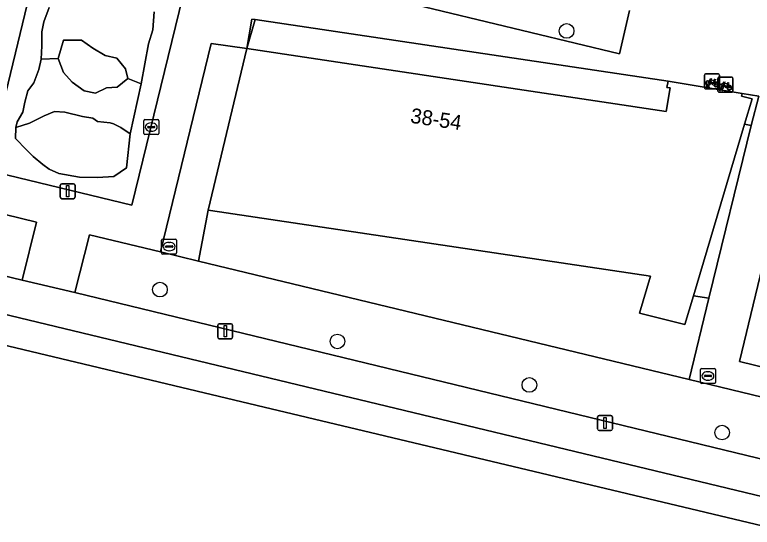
# Model space of a CAD drawing. Extents: x 162803 to 163818, y 381639 to 382475.
# Drawn here: x 163361.88 to 163411.14, y 382135.2 to 382169.41 of the extents above; entities that cross this region are included whole.
import ezdxf

# ---------------------------------------------------------------- set-up
doc = ezdxf.new("R2010")
doc.units = 0
for name, color, linetype in [('IMGEO_Boom', 7, 'Continuous'), ('IMGEO_Erf', 7, 'Continuous'), ('IMGEO_Fietsenrek', 7, 'Continuous'), ('IMGEO_Groenvoorziening', 7, 'Continuous'), ('IMGEO_Kolk', 7, 'Continuous'), ('IMGEO_Lichtmast', 7, 'Continuous'), ('IMGEO_Pand', 7, 'Continuous'), ('IMGEO_Pand_nummerreeks', 7, 'Continuous'), ('IMGEO_Pand_overbouw', 7, 'Continuous'), ('IMGEO_Parkeervlak_open', 7, 'Continuous'), ('IMGEO_Rioolput', 7, 'Continuous'), ('IMGEO_Voetpad_open', 7, 'Continuous')]:
    doc.layers.add(name, color=color, linetype=linetype)

msp = doc.modelspace()

# ---------------------------------------------------------------- linework, layer by layer
at = {"layer": 'IMGEO_Boom'}
for centre in [(163398.74, 382168.329), (163371.577, 382151.068), (163383.432, 382147.607), (163396.251, 382144.701), (163409.125, 382141.526)]:
    msp.add_circle(centre, 0.489, dxfattribs=at)
at = {"layer": 'IMGEO_Erf'}
msp.add_lwpolyline([(163374.957, 382156.347), (163374.799, 382156.371), (163374.154, 382152.972), (163406.922, 382145.077), (163408.24, 382150.498), (163407.206, 382150.656), (163406.631, 382148.735), (163403.598, 382149.483), (163404.091, 382151.13), (163404.338, 382151.955)], close=True, dxfattribs=at)
at = {"layer": 'IMGEO_Fietsenrek'}
for p, q in [((163407.948, 382164.538), (163407.948, 382165.379)), ((163407.948, 382165.379), (163407.948, 382164.538)), ((163408.023, 382165.463), (163408.864, 382165.463)), ((163408.864, 382165.463), (163408.023, 382165.463)), ((163408.845, 382164.319), (163408.845, 382165.16)), ((163408.845, 382165.16), (163408.845, 382164.319)), ((163408.92, 382165.244), (163409.761, 382165.244)), ((163409.761, 382165.244), (163408.92, 382165.244)), ((163408.948, 382165.388), (163408.948, 382164.547)), ((163408.948, 382164.547), (163408.948, 382165.388)), ((163409.845, 382165.169), (163409.845, 382164.328)), ((163409.845, 382164.328), (163409.845, 382165.169)), ((163408.075, 382164.547), (163408.114, 382164.707)), ((163408.144, 382164.695), (163408.109, 382164.547)), ((163408.186, 382164.719), (163408.185, 382164.723)), ((163408.227, 382164.547), (163408.193, 382164.689)), ((163408.217, 382164.73), (163408.218, 382164.723)), ((163408.225, 382164.693), (163408.26, 382164.547)), ((163408.635, 382165.012), (163408.671, 382164.917)), ((163409.532, 382164.793), (163409.568, 382164.698)), ((163408.873, 382164.463), (163408.032, 382164.463)), ((163408.032, 382164.463), (163408.873, 382164.463)), ((163408.109, 382164.547), (163408.075, 382164.547)), ((163408.26, 382164.547), (163408.227, 382164.547)), ((163409.77, 382164.244), (163408.929, 382164.244)), ((163408.929, 382164.244), (163409.77, 382164.244)), ((163408.972, 382164.328), (163409.011, 382164.488)), ((163409.006, 382164.328), (163408.972, 382164.328)), ((163409.041, 382164.476), (163409.006, 382164.328)), ((163409.083, 382164.5), (163409.082, 382164.504)), ((163409.124, 382164.328), (163409.09, 382164.47)), ((163409.114, 382164.511), (163409.115, 382164.504)), ((163409.122, 382164.474), (163409.157, 382164.328)), ((163409.157, 382164.328), (163409.124, 382164.328))]:
    msp.add_line(p, q, dxfattribs=at)
for points in [[(163408.261, 382164.989), (163408.356, 382165.153), (163408.442, 382165.139), (163408.444, 382165.13), (163408.388, 382165.119), (163408.361, 382165.074), (163408.617, 382165.033)], [(163408.617, 382165.033), (163408.642, 382165.082), (163408.636, 382165.086), (163408.613, 382165.09), (163408.601, 382165.097), (163408.6, 382165.1), (163408.602, 382165.105), (163408.697, 382165.09), (163408.699, 382165.08), (163408.689, 382165.067), (163408.677, 382165.061), (163408.663, 382165.067), (163408.635, 382165.012)], [(163408.282, 382164.937), (163408.23, 382164.847), (163408.19, 382164.822), (163408.191, 382164.869), (163408.246, 382164.963)], [(163408.557, 382164.745), (163408.507, 382164.745), (163408.316, 382164.996), (163408.297, 382164.964)], [(163408.604, 382165.008), (163408.347, 382165.049), (163408.33, 382165.02), (163408.497, 382164.8), (163408.604, 382165.008)], [(163408.652, 382164.91), (163408.622, 382164.987), (163408.513, 382164.769), (163408.556, 382164.769)], [(163408.586, 382164.769), (163408.706, 382164.768), (163408.662, 382164.882)], [(163408.682, 382164.889), (163408.737, 382164.744), (163408.587, 382164.744)], [(163409.179, 382164.718), (163409.127, 382164.628), (163409.087, 382164.603), (163409.088, 382164.65), (163409.143, 382164.744)], [(163409.158, 382164.77), (163409.253, 382164.934), (163409.339, 382164.92), (163409.341, 382164.911), (163409.285, 382164.9), (163409.258, 382164.855), (163409.514, 382164.814)], [(163409.454, 382164.526), (163409.404, 382164.526), (163409.213, 382164.777), (163409.194, 382164.745)], [(163409.501, 382164.789), (163409.244, 382164.83), (163409.227, 382164.801), (163409.394, 382164.581), (163409.501, 382164.789)], [(163409.549, 382164.691), (163409.519, 382164.768), (163409.41, 382164.55), (163409.453, 382164.55)], [(163409.483, 382164.55), (163409.603, 382164.549), (163409.559, 382164.663)], [(163409.579, 382164.67), (163409.634, 382164.525), (163409.484, 382164.525)], [(163409.514, 382164.814), (163409.539, 382164.863), (163409.533, 382164.867), (163409.51, 382164.871), (163409.498, 382164.878), (163409.497, 382164.881), (163409.499, 382164.886), (163409.594, 382164.871), (163409.596, 382164.861), (163409.586, 382164.848), (163409.574, 382164.842), (163409.56, 382164.848), (163409.532, 382164.793)]]:
    msp.add_lwpolyline(points, dxfattribs=at)
for centre, radius, start, end in [((163408.026, 382165.385), 0.0779, 92.4484, 184.2845), ((163408.026, 382165.385), 0.0779, 92.4484, 184.2845), ((163408.923, 382165.166), 0.0779, 92.4484, 184.2845), ((163408.923, 382165.166), 0.0779, 92.4484, 184.2845), ((163408.87, 382165.385), 0.0779, 2.4484, 94.2845), ((163408.87, 382165.385), 0.0779, 2.4484, 94.2845), ((163409.767, 382165.166), 0.0779, 2.4484, 94.2845), ((163409.767, 382165.166), 0.0779, 2.4484, 94.2845), ((163408.188, 382164.848), 0.159, 62.6766, 242.1369), ((163408.188, 382164.848), 0.129, 63.3192, 238.903), ((163408.168, 382164.719), 0.0499, 12.8025, 158.6934), ((163408.188, 382164.848), 0.159, 253.9967, 271.7867), ((163408.168, 382164.719), 0.0174, 12.8025, 163.4502), ((163408.188, 382164.848), 0.129, 253.415, 269.0204), ((163408.188, 382164.848), 0.129, 283.6043, 43.4302), ((163408.188, 382164.848), 0.159, 283.5766, 46.6042), ((163408.715, 382164.764), 0.159, 113.3408, 178.3217), ((163408.715, 382164.764), 0.159, 187.0065, 105.7708), ((163408.715, 382164.764), 0.129, 113.923, 177.9556), ((163408.715, 382164.764), 0.129, 188.6715, 104.5883), ((163409.085, 382164.629), 0.159, 62.6766, 242.1369), ((163409.085, 382164.629), 0.129, 63.3192, 238.903), ((163409.085, 382164.629), 0.129, 283.6043, 43.4302), ((163409.085, 382164.629), 0.159, 283.5766, 46.6042), ((163409.612, 382164.545), 0.159, 113.3408, 178.3217), ((163409.612, 382164.545), 0.159, 187.0065, 105.7708), ((163409.612, 382164.545), 0.129, 113.923, 177.9556), ((163409.612, 382164.545), 0.129, 188.6715, 104.5883), ((163408.026, 382164.541), 0.0779, 182.4484, 274.2845), ((163408.026, 382164.541), 0.0779, 182.4484, 274.2845), ((163408.923, 382164.322), 0.0779, 182.4484, 274.2845), ((163408.923, 382164.322), 0.0779, 182.4484, 274.2845), ((163408.87, 382164.541), 0.0779, 272.4484, 4.2845), ((163408.87, 382164.541), 0.0779, 272.4484, 4.2845), ((163409.065, 382164.5), 0.0499, 12.8025, 158.6934), ((163409.085, 382164.629), 0.159, 253.9967, 271.7867), ((163409.065, 382164.5), 0.0174, 12.8025, 163.4502), ((163409.085, 382164.629), 0.129, 253.415, 269.0204), ((163409.767, 382164.322), 0.0779, 272.4484, 4.2845), ((163409.767, 382164.322), 0.0779, 272.4484, 4.2845)]:
    msp.add_arc(centre, radius, start, end, dxfattribs=at)
at = {"layer": 'IMGEO_Groenvoorziening'}
for points in [[(163363.636, 382173.996), (163360.014, 382159.038), (163369.709, 382156.692), (163373.348, 382171.653)], [(163371.202, 382169.61), (163371.11, 382168.415), (163370.804, 382167.466), (163370.314, 382164.8), (163369.579, 382161.461), (163369.333, 382159.194), (163368.506, 382158.612), (163367.404, 382158.551), (163366.209, 382158.582), (163364.83, 382158.827), (163364.187, 382159.102), (163363.758, 382159.409), (163363.115, 382159.96), (163362.655, 382160.389), (163361.92, 382161.155), (163361.951, 382161.89), (163362.043, 382162.258), (163362.41, 382162.901), (163362.563, 382163.575), (163362.747, 382164.341), (163363.145, 382164.862), (163363.482, 382165.75), (163363.636, 382166.455), (163363.697, 382167.343), (163363.697, 382168.262), (163363.819, 382168.936), (163364.187, 382169.886)], [(163364.187, 382169.886), (163363.819, 382168.936), (163363.697, 382168.262), (163363.697, 382167.343), (163363.636, 382166.455), (163364.769, 382166.485), (163365.137, 382167.711), (163366.331, 382167.711), (163367.097, 382167.19), (163367.924, 382166.7), (163368.69, 382166.516), (163369.272, 382165.811), (163369.425, 382165.168), (163370.314, 382164.8), (163370.804, 382167.466), (163371.11, 382168.415), (163371.202, 382169.61)], [(163413.657, 382160.192), (163410.282, 382146.275), (163421.953, 382143.42), (163425.325, 382157.394)]]:
    msp.add_lwpolyline(points, dxfattribs=at)
for points in [[(163365.137, 382167.711), (163364.769, 382166.485), (163365.137, 382165.566), (163365.719, 382164.923), (163366.515, 382164.341), (163367.281, 382164.188), (163368.016, 382164.525), (163368.721, 382164.586), (163369.425, 382165.168), (163369.272, 382165.811), (163368.69, 382166.516), (163367.924, 382166.7), (163367.097, 382167.19), (163366.331, 382167.711)], [(163362.364, 382151.707), (163363.339, 382155.573), (163356.026, 382157.354), (163323.14, 382165.323), (163320.628, 382165.9), (163315.3, 382167.211), (163314.355, 382163.32), (163338.36, 382157.513)], [(163377.389, 382167.151), (163374.987, 382167.505), (163371.606, 382153.585), (163374.154, 382152.972), (163374.799, 382156.371)], [(163370.314, 382164.8), (163369.425, 382165.168), (163368.721, 382164.586), (163368.016, 382164.525), (163367.281, 382164.188), (163366.515, 382164.341), (163365.719, 382164.923), (163365.137, 382165.566), (163364.769, 382166.485), (163363.636, 382166.455), (163363.482, 382165.75), (163363.145, 382164.862), (163362.747, 382164.341), (163362.563, 382163.575), (163362.41, 382162.901), (163362.043, 382162.258), (163361.951, 382161.89), (163362.87, 382162.166), (163363.85, 382162.656), (163364.524, 382162.962), (163365.229, 382162.901), (163366.393, 382162.625), (163367.097, 382162.503), (163367.404, 382162.288), (163368.261, 382162.196), (163368.476, 382162.135), (163368.966, 382161.89), (163369.579, 382161.461)], [(163295.227, 382165.323), (163294.668, 382163.195), (163295.55, 382162.985), (163313.112, 382158.803), (163333.895, 382153.854), (163342.628, 382151.775), (163344.765, 382151.266), (163359.411, 382147.779), (163360.431, 382147.536), (163378.53, 382143.226), (163427.031, 382131.676), (163427.406, 382133.488), (163361, 382149.482), (163359.96, 382149.732), (163344.914, 382153.356), (163343.556, 382153.683), (163337.772, 382155.076), (163333.95, 382155.997)], [(163427.031, 382131.676), (163378.53, 382143.226), (163360.431, 382147.536), (163359.411, 382147.779), (163344.765, 382151.266), (163342.628, 382151.775), (163333.895, 382153.854), (163313.112, 382158.803), (163295.55, 382162.985), (163294.668, 382163.195), (163286.387, 382131.648), (163317.39, 382119.198), (163320.353, 382126.576), (163333.259, 382121.451), (163330.2, 382114.053), (163345.456, 382107.927), (163361.874, 382101.334), (163416.208, 382079.515), (163424.081, 382117.46)], [(163369.579, 382161.461), (163368.966, 382161.89), (163368.476, 382162.135), (163368.261, 382162.196), (163367.404, 382162.288), (163367.097, 382162.503), (163366.393, 382162.625), (163365.229, 382162.901), (163364.524, 382162.962), (163363.85, 382162.656), (163362.87, 382162.166), (163361.951, 382161.89), (163361.92, 382161.155), (163362.655, 382160.389), (163363.115, 382159.96), (163363.758, 382159.409), (163364.187, 382159.102), (163364.83, 382158.827), (163366.209, 382158.582), (163367.404, 382158.551), (163368.506, 382158.612), (163369.333, 382159.194)], [(163406.922, 382145.077), (163374.154, 382152.972), (163371.606, 382153.585), (163366.869, 382154.713), (163365.885, 382150.868), (163412.973, 382139.449), (163413.921, 382143.368)]]:
    msp.add_lwpolyline(points, close=True, dxfattribs=at)
at = {"layer": 'IMGEO_Kolk'}
for p, q in [((163370.495, 382161.488), (163370.495, 382162.34)), ((163370.57, 382162.414), (163371.422, 382162.414)), ((163370.983, 382162.194), (163371.008, 382162.194)), ((163371.496, 382162.34), (163371.496, 382161.488)), ((163370.754, 382161.908), (163370.754, 382161.92)), ((163371.192, 382161.871), (163370.794, 382161.871)), ((163370.797, 382161.957), (163371.195, 382161.957)), ((163371.238, 382161.92), (163371.238, 382161.908)), ((163371.422, 382161.414), (163370.57, 382161.414)), ((163371.006, 382161.634), (163370.981, 382161.634))]:
    msp.add_line(p, q, dxfattribs=at)
for points in [[(163370.495, 382161.488), (163370.495, 382162.34)], [(163370.57, 382162.414), (163371.422, 382162.414)], [(163371.496, 382162.34), (163371.496, 382161.488)], [(163371.422, 382161.414), (163370.57, 382161.414)]]:
    msp.add_lwpolyline(points, dxfattribs=at)
for centre, radius, start, end in [((163370.572, 382162.338), 0.0765, 91.552, 178.448), ((163370.572, 382162.338), 0.0765, 91.552, 178.448), ((163371.42, 382162.338), 0.0765, 1.552, 88.448), ((163371.42, 382162.338), 0.0765, 1.552, 88.448), ((163370.794, 382161.917), 0.0403, 85.8775, 175.7526), ((163370.791, 382161.907), 0.0366, 178.938, 274.7102), ((163371.195, 382161.914), 0.043, 264.8664, 352.4533), ((163371.199, 382161.919), 0.0386, 1.7309, 96.639), ((163370.572, 382161.49), 0.0765, 181.552, 268.448), ((163370.572, 382161.49), 0.0765, 181.552, 268.448), ((163371.42, 382161.49), 0.0765, 271.552, 358.448), ((163371.42, 382161.49), 0.0765, 271.552, 358.448)]:
    msp.add_arc(centre, radius, start, end, dxfattribs=at)
for centre, major_axis, ratio, start_param, end_param in [((163370.982, 382161.914), (-0.387, 0.002), 0.722429, 4.712389, 7.853982), ((163371.007, 382161.914), (-0.39, 0.002), 0.717154, 1.570796, 4.712389)]:
    msp.add_ellipse(centre, major_axis=major_axis, ratio=ratio, start_param=start_param, end_param=end_param, dxfattribs=at)
at = {"layer": 'IMGEO_Lichtmast'}
for p, q in [((163364.918, 382157.236), (163364.918, 382158.036)), ((163364.918, 382158.036), (163364.918, 382157.236)), ((163365.018, 382158.136), (163365.808, 382158.136)), ((163365.808, 382158.136), (163365.018, 382158.136)), ((163365.908, 382158.036), (163365.908, 382157.236)), ((163365.908, 382157.236), (163365.908, 382158.036)), ((163365.808, 382157.136), (163365.018, 382157.136)), ((163365.018, 382157.136), (163365.808, 382157.136)), ((163375.443, 382147.888), (163375.443, 382148.688)), ((163375.443, 382148.688), (163375.443, 382147.888)), ((163375.543, 382148.788), (163376.333, 382148.788)), ((163376.333, 382148.788), (163375.543, 382148.788)), ((163376.433, 382148.688), (163376.433, 382147.888)), ((163376.433, 382147.888), (163376.433, 382148.688)), ((163376.333, 382147.788), (163375.543, 382147.788)), ((163375.543, 382147.788), (163376.333, 382147.788)), ((163400.808, 382141.765), (163400.808, 382142.565)), ((163400.808, 382142.565), (163400.808, 382141.765)), ((163400.908, 382142.665), (163401.698, 382142.665)), ((163401.698, 382142.665), (163400.908, 382142.665)), ((163401.798, 382142.565), (163401.798, 382141.765)), ((163401.798, 382141.765), (163401.798, 382142.565)), ((163401.698, 382141.665), (163400.908, 382141.665)), ((163400.908, 382141.665), (163401.698, 382141.665))]:
    msp.add_line(p, q, dxfattribs=at)
for points in [[(163365.338, 382158.011), (163365.488, 382158.011), (163365.488, 382157.261), (163365.338, 382157.261), (163365.338, 382158.011)], [(163375.863, 382148.663), (163376.013, 382148.663), (163376.013, 382147.913), (163375.863, 382147.913), (163375.863, 382148.663)], [(163401.228, 382142.54), (163401.378, 382142.54), (163401.378, 382141.79), (163401.228, 382141.79), (163401.228, 382142.54)]]:
    msp.add_lwpolyline(points, dxfattribs=at)
for centre, start, end in [((163365.018, 382158.036), 90, 180), ((163365.018, 382158.036), 90, 180), ((163365.808, 382158.036), 0, 90), ((163365.808, 382158.036), 360, 90), ((163365.018, 382157.236), 180, 270), ((163365.018, 382157.236), 180, 270), ((163365.808, 382157.236), 270, 0), ((163365.808, 382157.236), 270, 0), ((163375.543, 382148.688), 90, 180), ((163375.543, 382148.688), 90, 180), ((163376.333, 382148.688), 0, 90), ((163376.333, 382148.688), 360, 90), ((163375.543, 382147.888), 180, 270), ((163375.543, 382147.888), 180, 270), ((163376.333, 382147.888), 270, 0), ((163376.333, 382147.888), 270, 0), ((163400.908, 382142.565), 90, 180), ((163400.908, 382142.565), 90, 180), ((163401.698, 382142.565), 0, 90), ((163401.698, 382142.565), 360, 90), ((163400.908, 382141.765), 180, 270), ((163400.908, 382141.765), 180, 270), ((163401.698, 382141.765), 270, 0), ((163401.698, 382141.765), 270, 0)]:
    msp.add_arc(centre, 0.1, start, end, dxfattribs=at)
at = {"layer": 'IMGEO_Pand'}
msp.add_lwpolyline([(163407.206, 382150.656), (163410.631, 382162.099), (163411.138, 382163.792), (163410.432, 382163.969), (163410.462, 382164.153), (163405.517, 382164.971), (163405.442, 382164.556), (163405.658, 382164.528), (163405.399, 382162.964), (163377.389, 382167.151), (163374.799, 382156.371), (163374.957, 382156.347), (163404.338, 382151.955), (163404.091, 382151.13), (163403.598, 382149.483), (163406.631, 382148.735)], close=True, dxfattribs=at)
at = {"layer": 'IMGEO_Pand_overbouw'}
msp.add_lwpolyline([(163411.056, 382162.02), (163410.631, 382162.099), (163407.206, 382150.656), (163408.24, 382150.498)], close=True, dxfattribs=at)
at = {"layer": 'IMGEO_Parkeervlak_open'}
msp.add_lwpolyline([(163379.275, 382175.422), (163378.585, 382172.515), (163402.273, 382166.808), (163402.95, 382169.707)], dxfattribs=at)
at = {"layer": 'IMGEO_Rioolput'}
for p, q in [((163371.691, 382153.511), (163371.691, 382154.363)), ((163371.766, 382154.437), (163372.618, 382154.437)), ((163372.692, 382154.363), (163372.692, 382153.511)), ((163371.95, 382153.931), (163371.95, 382153.943)), ((163372.388, 382153.894), (163371.99, 382153.894)), ((163371.993, 382153.98), (163372.391, 382153.98)), ((163372.179, 382154.217), (163372.204, 382154.217)), ((163372.434, 382153.943), (163372.434, 382153.931)), ((163372.618, 382153.437), (163371.766, 382153.437)), ((163372.202, 382153.657), (163372.177, 382153.657)), ((163407.682, 382144.876), (163407.682, 382145.728)), ((163407.757, 382145.802), (163408.609, 382145.802)), ((163408.17, 382145.582), (163408.195, 382145.582)), ((163408.683, 382145.728), (163408.683, 382144.876)), ((163407.941, 382145.296), (163407.941, 382145.308)), ((163408.379, 382145.259), (163407.981, 382145.259)), ((163407.984, 382145.345), (163408.382, 382145.345)), ((163408.193, 382145.022), (163408.168, 382145.022)), ((163408.425, 382145.308), (163408.425, 382145.296)), ((163408.609, 382144.802), (163407.757, 382144.802))]:
    msp.add_line(p, q, dxfattribs=at)
for points in [[(163371.691, 382153.511), (163371.691, 382154.363)], [(163371.766, 382154.437), (163372.618, 382154.437)], [(163372.692, 382154.363), (163372.692, 382153.511)], [(163372.618, 382153.437), (163371.766, 382153.437)], [(163407.682, 382144.876), (163407.682, 382145.728)], [(163407.757, 382145.802), (163408.609, 382145.802)], [(163408.683, 382145.728), (163408.683, 382144.876)], [(163408.609, 382144.802), (163407.757, 382144.802)]]:
    msp.add_lwpolyline(points, dxfattribs=at)
for centre, radius, start, end in [((163371.768, 382154.361), 0.0765, 91.552, 178.448), ((163371.768, 382154.361), 0.0765, 91.552, 178.448), ((163372.616, 382154.361), 0.0765, 1.552, 88.448), ((163372.616, 382154.361), 0.0765, 1.552, 88.448), ((163371.99, 382153.94), 0.0403, 85.8775, 175.7526), ((163371.987, 382153.93), 0.0366, 178.938, 274.7102), ((163372.391, 382153.937), 0.043, 264.8664, 352.4533), ((163372.395, 382153.942), 0.0386, 1.7309, 96.639), ((163371.768, 382153.513), 0.0765, 181.552, 268.448), ((163371.768, 382153.513), 0.0765, 181.552, 268.448), ((163372.616, 382153.513), 0.0765, 271.552, 358.448), ((163372.616, 382153.513), 0.0765, 271.552, 358.448), ((163407.759, 382145.726), 0.0765, 91.552, 178.448), ((163407.759, 382145.726), 0.0765, 91.552, 178.448), ((163408.607, 382145.726), 0.0765, 1.552, 88.448), ((163408.607, 382145.726), 0.0765, 1.552, 88.448), ((163407.981, 382145.305), 0.0403, 85.8775, 175.7526), ((163407.978, 382145.295), 0.0366, 178.938, 274.7102), ((163408.382, 382145.302), 0.043, 264.8664, 352.4533), ((163408.386, 382145.307), 0.0386, 1.7309, 96.639), ((163407.759, 382144.878), 0.0765, 181.552, 268.448), ((163407.759, 382144.878), 0.0765, 181.552, 268.448), ((163408.607, 382144.878), 0.0765, 271.552, 358.448), ((163408.607, 382144.878), 0.0765, 271.552, 358.448)]:
    msp.add_arc(centre, radius, start, end, dxfattribs=at)
for centre, major_axis, ratio, start_param, end_param in [((163372.178, 382153.937), (-0.387, 0.002), 0.722429, 4.712389, 7.853982), ((163372.203, 382153.937), (-0.39, 0.002), 0.717154, 1.570796, 4.712389), ((163408.169, 382145.302), (-0.387, 0.002), 0.722429, 4.712389, 7.853982), ((163408.194, 382145.302), (-0.39, 0.002), 0.717154, 1.570796, 4.712389)]:
    msp.add_ellipse(centre, major_axis=major_axis, ratio=ratio, start_param=start_param, end_param=end_param, dxfattribs=at)
at = {"layer": 'IMGEO_Voetpad_open'}
for points in [[(163402.95, 382169.707), (163402.273, 382166.808), (163378.585, 382172.515), (163379.275, 382175.422)], [(163369.709, 382156.692), (163360.014, 382159.038), (163363.636, 382173.996)], [(163373.348, 382171.653), (163369.709, 382156.692)], [(163356.026, 382157.354), (163363.339, 382155.573), (163362.364, 382151.707), (163365.885, 382150.868), (163366.869, 382154.713), (163371.606, 382153.585), (163374.987, 382167.505), (163377.389, 382167.151), (163377.71, 382169.118), (163377.926, 382169.086), (163405.517, 382164.971), (163410.462, 382164.153), (163411.572, 382163.984), (163411.056, 382162.02), (163408.24, 382150.498), (163406.922, 382145.077), (163413.921, 382143.368)], [(163417.441, 382142.486), (163419.752, 382141.912), (163421.49, 382141.5), (163421.953, 382143.42), (163410.282, 382146.275), (163413.657, 382160.192)]]:
    msp.add_lwpolyline(points, dxfattribs=at)
for points in [[(163377.389, 382167.151), (163377.926, 382169.086), (163377.71, 382169.118)], [(163377.926, 382169.086), (163377.389, 382167.151), (163405.399, 382162.964), (163405.658, 382164.528), (163405.442, 382164.556), (163405.517, 382164.971)], [(163410.462, 382164.153), (163410.432, 382163.969), (163411.138, 382163.792), (163410.631, 382162.099), (163411.056, 382162.02), (163411.572, 382163.984)], [(163411.056, 382162.02), (163410.631, 382162.099), (163407.206, 382150.656), (163408.24, 382150.498)], [(163365.885, 382150.868), (163362.364, 382151.707), (163338.36, 382157.513), (163337.772, 382155.076), (163343.556, 382153.683), (163344.914, 382153.356), (163359.96, 382149.732), (163361, 382149.482), (163427.406, 382133.488), (163429.448, 382132.996), (163431.522, 382132.438), (163444.984, 382129.085), (163448.513, 382128.232), (163449.952, 382127.884), (163450.206, 382127.822), (163450.835, 382130.483), (163449.223, 382130.905), (163448.735, 382131.02), (163447.733, 382131.255), (163418.029, 382138.23), (163416.483, 382138.612), (163412.973, 382139.449)]]:
    msp.add_lwpolyline(points, close=True, dxfattribs=at)

# ---------------------------------------------------------------- texts
at = {"layer": 'IMGEO_Pand_nummerreeks'}
msp.add_text('38-54', height=1, rotation=351.4982, dxfattribs=at).set_placement((163388.262, 382162.209))

doc.saveas('drawing.dxf')
